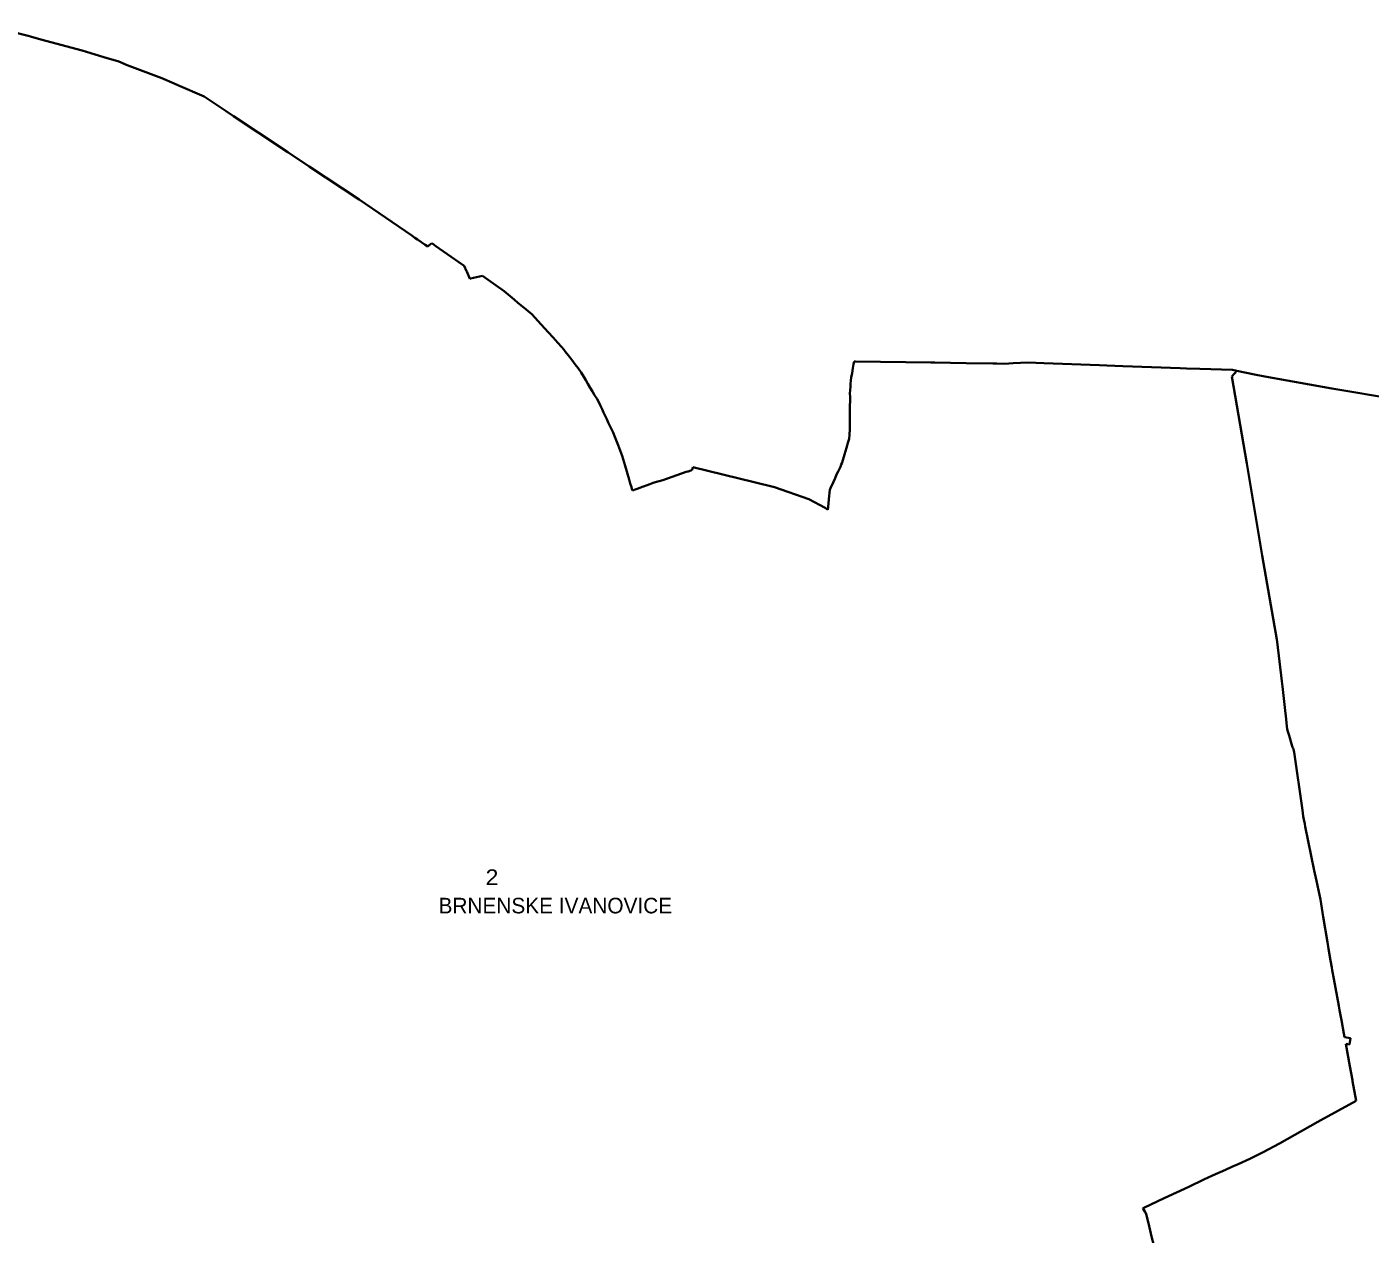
# Model space of a CAD drawing. Extents: x -610940 to -588976, y -1170376 to -1149800.
# Drawn here: x -596623 to -594465, y -1165505 to -1163566 of the extents above; entities that cross this region are included whole.
import ezdxf

# ---------------------------------------------------------------- set-up
doc = ezdxf.new("R2010")
doc.units = 0
doc.header["$LTSCALE"] = 10
doc.layers.add('54', color=7, linetype='Continuous', lineweight=35)
doc.layers.add('55', color=7, linetype='Continuous')
doc.layers.add('56', color=7, linetype='Continuous')

msp = doc.modelspace()

# ---------------------------------------------------------------- linework, layer by layer
at = {"layer": '54'}
for p, q in [((-596534.1, -1163604.42), (-596600.91, -1163586.27)), ((-596338.28, -1163678.34), (-596380.4, -1163659.9)), ((-596089.4, -1163843.24), (-596169.46, -1163790.57)), ((-596004.96, -1163901.29), (-596089.4, -1163843.24)), ((-595999.83, -1163904.81), (-596004.96, -1163901.29)), ((-595995.56, -1163907.75), (-595999.83, -1163904.81)), ((-595983.12, -1163916.36), (-595995.56, -1163907.75)), ((-595979.16, -1163919.1), (-595983.12, -1163916.36)), ((-595977.31, -1163917.57), (-595979.16, -1163919.1)), ((-595972.64, -1163913.7), (-595977.31, -1163917.57)), ((-595970.95, -1163914.9), (-595972.64, -1163913.7)), ((-595965.93, -1163918.47), (-595970.95, -1163914.9)), ((-595929.41, -1163944.41), (-595965.93, -1163918.47)), ((-595920.56, -1163950.06), (-595929.41, -1163944.41)), ((-595916.84, -1163958.4), (-595920.56, -1163950.06)), ((-595916.58, -1163959.04), (-595916.84, -1163958.4)), ((-595911.73, -1163970.88), (-595916.58, -1163959.04)), ((-595891.45, -1163965.87), (-595910.66, -1163970.51)), ((-595856.56, -1163990.84), (-595891.45, -1163965.87)), ((-595910.66, -1163970.51), (-595911.73, -1163970.88)), ((-595840.26, -1164004.34), (-595856.56, -1163990.84)), ((-595834.27, -1164009.46), (-595840.26, -1164004.34)), ((-595827.17, -1164015.52), (-595834.27, -1164009.46)), ((-595812.2, -1164027.51), (-595827.17, -1164015.52)), ((-595811.31, -1164028.23), (-595812.2, -1164027.51)), ((-595802.12, -1164038.48), (-595811.31, -1164028.23)), ((-595785.49, -1164056.75), (-595802.12, -1164038.48)), ((-595777.93, -1164065.12), (-595785.49, -1164056.75)), ((-595770.26, -1164073.58), (-595777.93, -1164065.12)), ((-595764.1, -1164080.14), (-595770.26, -1164073.58)), ((-595760.79, -1164084.62), (-595764.1, -1164080.14)), ((-595758.36, -1164087.81), (-595760.79, -1164084.62)), ((-595753.81, -1164093.75), (-595758.36, -1164087.81)), ((-595747.95, -1164100.89), (-595753.81, -1164093.75)), ((-595742.48, -1164108.4), (-595747.95, -1164100.89)), ((-595737.59, -1164114.53), (-595742.48, -1164108.4)), ((-595732.58, -1164121.18), (-595737.59, -1164114.53)), ((-595296.39, -1164114.19), (-595297.5, -1164122.56)), ((-595295.15, -1164108.1), (-595296.39, -1164114.19)), ((-595294.36, -1164103.67), (-595295.15, -1164108.1)), ((-595291.82, -1164103.7), (-595294.36, -1164103.67)), ((-595171, -1164105.36), (-595291.82, -1164103.7)), ((-595164.36, -1164105.47), (-595171, -1164105.36)), ((-595114.07, -1164106.32), (-595164.36, -1164105.47)), ((-595071.46, -1164107.03), (-595114.07, -1164106.32)), ((-595065.15, -1164107.14), (-595071.46, -1164107.03)), ((-595052.27, -1164107.34), (-595065.15, -1164107.14)), ((-595045.9, -1164106.95), (-595052.27, -1164107.34)), ((-595038.67, -1164106.5), (-595045.9, -1164106.95)), ((-595015.26, -1164105.05), (-595038.67, -1164106.5)), ((-594989.44, -1164106.12), (-595015.26, -1164105.05)), ((-594899.99, -1164109.82), (-594989.44, -1164106.12)), ((-594888.27, -1164110.31), (-594899.99, -1164109.82)), ((-594862.39, -1164111.38), (-594888.27, -1164110.31)), ((-594770.72, -1164114.44), (-594862.39, -1164111.38)), ((-594760.06, -1164114.8), (-594770.72, -1164114.44)), ((-594739, -1164115.5), (-594760.06, -1164114.8)), ((-594686.2, -1164117.27), (-594739, -1164115.5)), ((-594679.69, -1164118.66), (-594686.2, -1164117.27)), ((-594679.69, -1164118.66), (-594683.29, -1164122.99)), ((-595728.61, -1164128.24), (-595732.58, -1164121.18)), ((-595725.36, -1164133.45), (-595728.61, -1164128.24)), ((-595721.77, -1164139.49), (-595725.36, -1164133.45)), ((-595718.07, -1164145.86), (-595721.77, -1164139.49)), ((-595299.86, -1164139.38), (-595300.19, -1164144.22)), ((-595299.31, -1164134.34), (-595299.86, -1164139.38)), ((-595298.78, -1164129.54), (-595299.31, -1164134.34)), ((-595297.5, -1164122.56), (-595298.78, -1164129.54)), ((-594687.41, -1164127.94), (-594683.29, -1164122.99)), ((-594687.41, -1164127.94), (-594663.63, -1164267.57)), ((-595714.52, -1164151.78), (-595718.07, -1164145.86)), ((-595711.05, -1164157.91), (-595714.52, -1164151.78)), ((-595707.78, -1164163.32), (-595711.05, -1164157.91)), ((-595300.19, -1164144.22), (-595301.01, -1164154.91)), ((-595301.01, -1164154.91), (-595300.83, -1164160.59)), ((-595300.83, -1164160.59), (-595300.85, -1164168.32)), ((-595704.31, -1164169), (-595707.78, -1164163.32)), ((-595701.63, -1164174.73), (-595704.31, -1164169)), ((-595699.11, -1164180.32), (-595701.63, -1164174.73)), ((-595696.79, -1164185.52), (-595699.11, -1164180.32)), ((-595300.99, -1164173.2), (-595301.2, -1164182.36)), ((-595301.2, -1164182.36), (-595301.17, -1164188.38)), ((-595300.85, -1164168.32), (-595300.99, -1164173.2)), ((-595694.22, -1164190.85), (-595696.79, -1164185.52)), ((-595691.59, -1164196.34), (-595694.22, -1164190.85)), ((-595689.2, -1164201.46), (-595691.59, -1164196.34)), ((-595686.57, -1164207.18), (-595689.2, -1164201.46)), ((-595301.17, -1164188.38), (-595301.05, -1164197.39)), ((-595301.05, -1164197.39), (-595300.87, -1164203.33)), ((-595300.88, -1164203.86), (-595300.97, -1164208.28)), ((-595300.87, -1164203.33), (-595300.88, -1164203.86)), ((-595684.06, -1164212.57), (-595686.57, -1164207.18)), ((-595681.36, -1164217.97), (-595684.06, -1164212.57)), ((-595678.67, -1164224.77), (-595681.36, -1164217.97)), ((-595676.5, -1164230.26), (-595678.67, -1164224.77)), ((-595301.84, -1164221.45), (-595302.39, -1164227.94)), ((-595301.29, -1164212.62), (-595301.84, -1164221.45)), ((-595300.97, -1164208.28), (-595301.29, -1164212.62)), ((-595673.52, -1164237.8), (-595676.5, -1164230.26)), ((-595666.72, -1164255.01), (-595673.52, -1164237.8)), ((-595306.42, -1164242.2), (-595309.56, -1164253.06)), ((-595305.41, -1164238.44), (-595306.42, -1164242.2)), ((-595304.15, -1164234.15), (-595305.41, -1164238.44)), ((-595302.39, -1164227.94), (-595304.15, -1164234.15)), ((-595661.99, -1164271.05), (-595666.72, -1164255.01)), ((-595314.87, -1164269.28), (-595316.36, -1164272.68)), ((-595313.44, -1164266.34), (-595314.87, -1164269.28)), ((-595313.25, -1164265.82), (-595313.44, -1164266.34)), ((-595309.56, -1164253.06), (-595313.25, -1164265.82)), ((-595655.65, -1164293.25), (-595661.99, -1164271.05)), ((-595564.01, -1164281.13), (-595601.57, -1164294.16)), ((-595561.4, -1164280.21), (-595564.01, -1164281.13)), ((-595561.06, -1164280.09), (-595561.4, -1164280.21)), ((-595556.66, -1164278.55), (-595561.06, -1164280.09)), ((-595554.22, -1164277.69), (-595556.66, -1164278.55)), ((-595553.41, -1164273.41), (-595554.22, -1164277.69)), ((-595454.75, -1164297.44), (-595553.41, -1164273.41)), ((-595324.89, -1164290.91), (-595327.58, -1164296.9)), ((-595322.31, -1164285.42), (-595324.89, -1164290.91)), ((-595320.02, -1164280.09), (-595322.31, -1164285.42)), ((-595316.36, -1164272.68), (-595320.02, -1164280.09)), ((-595653.8, -1164299.72), (-595655.65, -1164293.25)), ((-595652.43, -1164304.14), (-595653.8, -1164299.72)), ((-595650.63, -1164309.95), (-595652.43, -1164304.14)), ((-595650.37, -1164310.79), (-595650.63, -1164309.95)), ((-595644.11, -1164308.61), (-595650.37, -1164310.79)), ((-595637.06, -1164306.01), (-595644.11, -1164308.61)), ((-595634.69, -1164305.16), (-595637.06, -1164306.01)), ((-595632.35, -1164304.32), (-595634.69, -1164305.16)), ((-595626.76, -1164302.31), (-595632.35, -1164304.32)), ((-595615.4, -1164298.06), (-595626.76, -1164302.31)), ((-595601.57, -1164294.16), (-595615.4, -1164298.06)), ((-595422.13, -1164305.39), (-595454.75, -1164297.44)), ((-595367.14, -1164324.86), (-595422.13, -1164305.39)), ((-595333.43, -1164309.84), (-595334.79, -1164324.93)), ((-595330.9, -1164304.22), (-595333.43, -1164309.84)), ((-595329.19, -1164300.45), (-595330.9, -1164304.22)), ((-595327.58, -1164296.9), (-595329.19, -1164300.45)), ((-595340.84, -1164338.56), (-595367.14, -1164324.86)), ((-595335.41, -1164331.87), (-595336.49, -1164341.88)), ((-595334.79, -1164324.93), (-595335.41, -1164331.87)), ((-595336.49, -1164341.88), (-595340.84, -1164338.56)), ((-594607.31, -1164617.16), (-594606.3, -1164625.87)), ((-594602.41, -1164659.12), (-594606.3, -1164625.87)), ((-594602.41, -1164659.12), (-594600.27, -1164678.31)), ((-594595.65, -1164704.47), (-594598.29, -1164696.13)), ((-594595.65, -1164704.47), (-594591.58, -1164717.58)), ((-594590.4, -1164721.39), (-594591.58, -1164717.58)), ((-594590.4, -1164721.39), (-594589.83, -1164722.85)), ((-594589.83, -1164722.85), (-594589.28, -1164724.23)), ((-594589.19, -1164724.46), (-594589.28, -1164724.23)), ((-594589.19, -1164724.46), (-594589.11, -1164724.74)), ((-594587.36, -1164731), (-594589.11, -1164724.74)), ((-594587.36, -1164731), (-594574.18, -1164824.04)), ((-594574.18, -1164824.04), (-594572.77, -1164834.01)), ((-594570.37, -1164846.44), (-594569.57, -1164850.33)), ((-594555.08, -1164920.99), (-594569.57, -1164850.33)), ((-594555.08, -1164920.99), (-594551.63, -1164937.8)), ((-594533.99, -1165036.45), (-594532.09, -1165047.09)), ((-594528.75, -1165065.86), (-594532.09, -1165047.09)), ((-594528.75, -1165065.86), (-594526.76, -1165077.06)), ((-594526.05, -1165081.03), (-594526.76, -1165077.06)), ((-594526.05, -1165081.03), (-594523.52, -1165095.04)), ((-594514.44, -1165145.34), (-594511.52, -1165161.49)), ((-594507.61, -1165183.14), (-594511.52, -1165161.49)), ((-594507.61, -1165183.14), (-594506.51, -1165189.04)), ((-594504.55, -1165199.63), (-594497.95, -1165235.18)), ((-594493.72, -1165257.94), (-594497.95, -1165235.18)), ((-594491.78, -1165268.34), (-594487.55, -1165291.14)), ((-594487.55, -1165291.14), (-594544.42, -1165322.18)), ((-594549.36, -1165324.88), (-594544.42, -1165322.18)), ((-594637.12, -1165373.36), (-594652.09, -1165381.23))]:
    msp.add_line(p, q, dxfattribs=at)
for points in [[(-596668.6, -1163566.25), (-596666.1, -1163567.3), (-596657.88, -1163569.87), (-596647.96, -1163572.99), (-596640.9, -1163575.2), (-596637.91, -1163576.14), (-596636.07, -1163576.71), (-596620.95, -1163580.82), (-596617.37, -1163581.79), (-596600.91, -1163586.27)], [(-596534.1, -1163604.42), (-596499.53, -1163614.72), (-596475.14, -1163622.06), (-596462.06, -1163627.74), (-596406.33, -1163648.67), (-596386.48, -1163657.24), (-596380.4, -1163659.9)], [(-596338.28, -1163678.34), (-596302.73, -1163701.52), (-596290.96, -1163709.57), (-596251.76, -1163735.73), (-596203.85, -1163767.69), (-596169.46, -1163790.57)], [(-594289.35, -1164187.66), (-594422.05, -1164164.73), (-594424.62, -1164164.3), (-594526.67, -1164146.81), (-594634.24, -1164127.9), (-594651.29, -1164124.79), (-594679.69, -1164118.66)], [(-594663.63, -1164267.57), (-594640.12, -1164405.58), (-594638.64, -1164415.25), (-594615.16, -1164550)], [(-594615.16, -1164550), (-594614.73, -1164553.66), (-594607.31, -1164617.16)], [(-594600.27, -1164678.31), (-594598.98, -1164689.94), (-594598.59, -1164693.47), (-594598.29, -1164696.13)], [(-594572.77, -1164834.01), (-594571.89, -1164839.02), (-594570.37, -1164846.44)], [(-594551.63, -1164937.8), (-594545.23, -1164967.71), (-594541.02, -1164995.53), (-594533.99, -1165036.45)], [(-594523.52, -1165095.04), (-594515.71, -1165138.31), (-594514.44, -1165145.34)], [(-594506.51, -1165189.04), (-594497.06, -1165190.53), (-594498.47, -1165200.59), (-594504.55, -1165199.63)], [(-594493.72, -1165257.94), (-594493.42, -1165259.57), (-594492.32, -1165265.44), (-594491.78, -1165268.34)], [(-594549.36, -1165324.88), (-594611.09, -1165359.39), (-594637.12, -1165373.36)], [(-594652.09, -1165381.23), (-594658.58, -1165384.3), (-594677.13, -1165392.8), (-594687.51, -1165397.3), (-594697.75, -1165401.86), (-594718.36, -1165410.78), (-594732.36, -1165417.49), (-594756.71, -1165429.15), (-594796.27, -1165447.68), (-594828.66, -1165462.76), (-594830.59, -1165463.66)], [(-594791.66, -1165609.79), (-594800.46, -1165573.92), (-594803.27, -1165562.5), (-594806.03, -1165551.22), (-594813.05, -1165522.65), (-594815.85, -1165511.21), (-594820.44, -1165492.51), (-594824.93, -1165472.46), (-594827.36, -1165468.68), (-594829.09, -1165466), (-594830.59, -1165463.66)]]:
    msp.add_lwpolyline(points, dxfattribs=at)

# ---------------------------------------------------------------- texts
at = {"layer": '55'}
msp.add_text('BRNENSKE IVANOVICE', height=25, dxfattribs=at).set_placement((-595961.84, -1164990.04))
at = {"layer": '56', "width": 1.1}
msp.add_text('2 ', height=25, dxfattribs=at).set_placement((-595886.2, -1164944.38))

doc.saveas('drawing.dxf')
